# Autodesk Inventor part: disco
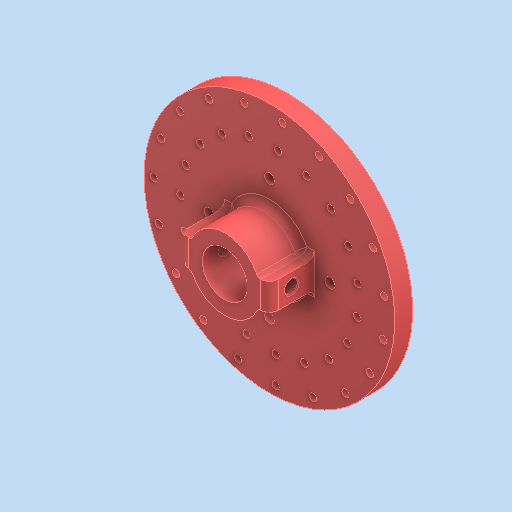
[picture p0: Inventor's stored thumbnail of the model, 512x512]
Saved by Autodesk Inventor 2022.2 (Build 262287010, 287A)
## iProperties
Created: 2025-03
Part Number: disco
Material: Plastica ABS
Document SubType Name: Modeling
Designer: 18907419
Density: 1.06 g/cm^3
Appearance: Default
Author: 18907419
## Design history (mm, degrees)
feature "Solido1"
node "Solido2"
